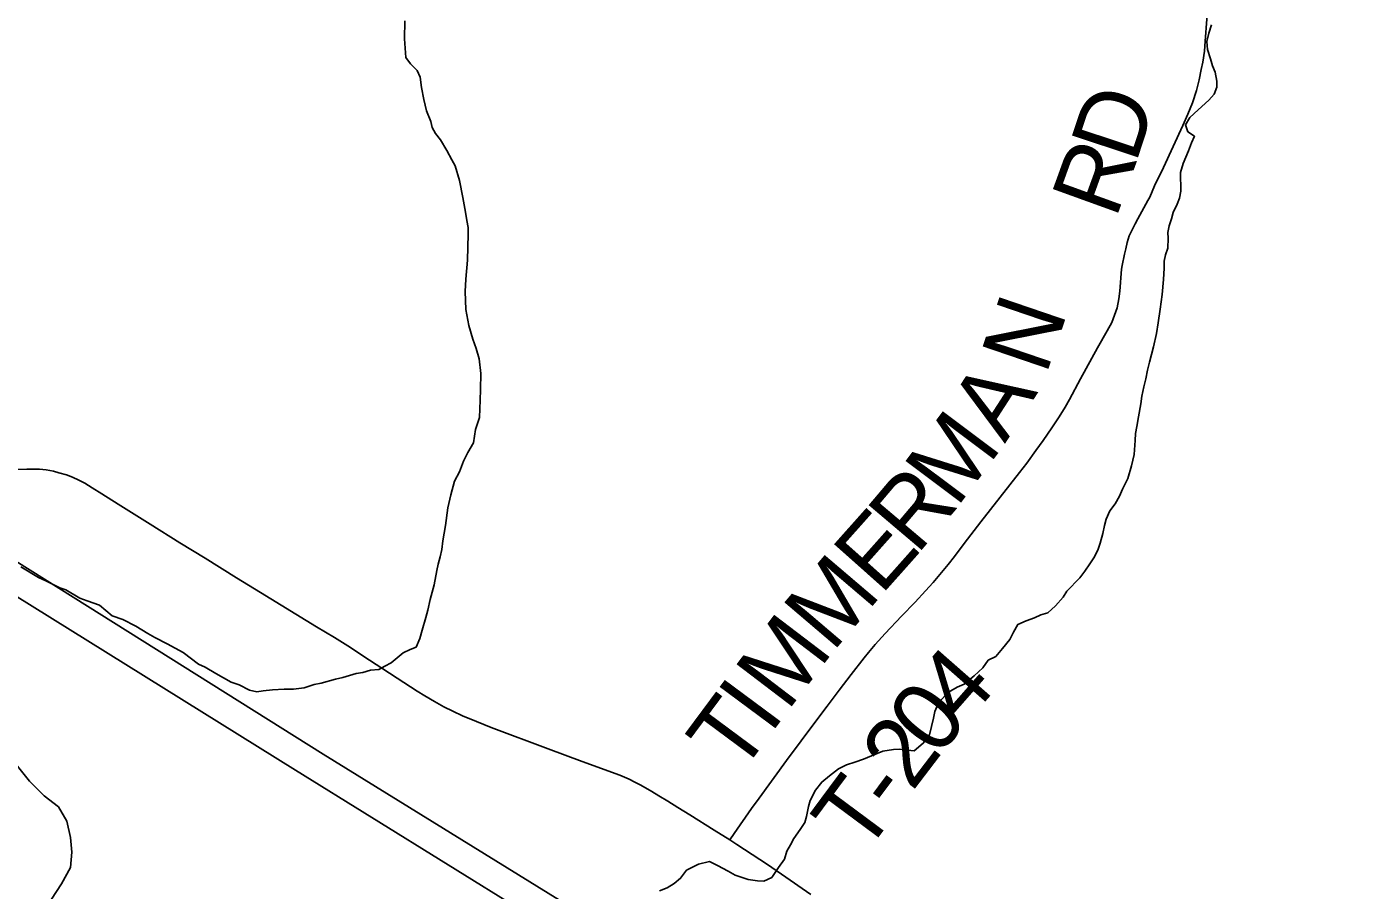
# Model space of a CAD drawing. Extents: x 0 to 34, y 0 to 22.
# Drawn here: x 6.594 to 7.678, y 17.126 to 17.833 of the extents above; entities that cross this region are included whole.
import ezdxf

# ---------------------------------------------------------------- set-up
doc = ezdxf.new("R2010")
doc.units = 0
for name, color, linetype in [('GM_X_County_Road', 7, 'Continuous'), ('GM_X_Interchange_Ramps', 7, 'Continuous'), ('GM_X_Interstate_Route', 7, 'Continuous'), ('GM_X_Section', 7, 'Continuous'), ('GM_X_Township_Road_Text', 7, 'Continuous'), ('GM_X_US_Location', 7, 'Continuous')]:
    doc.layers.add(name, color=color, linetype=linetype)

msp = doc.modelspace()

# ---------------------------------------------------------------- linework, layer by layer
at = {"layer": 'GM_X_County_Road'}
for points in [[(8.9, 16.3458), (8.8896, 16.3484), (8.8415, 16.3566), (8.7835, 16.3626), (8.6949, 16.3631), (8.0785, 16.3449), (8.0171, 16.3505), (7.9686, 16.3596), (7.9232, 16.3737), (7.8664, 16.3974), (7.8219, 16.4192), (7.7822, 16.4429), (7.7542, 16.4676), (7.7187, 16.4982), (7.6774, 16.5465), (7.4755, 16.7917), (7.4147, 16.863), (7.366, 16.9092), (7.315, 16.9447), (7.2325, 16.9942), (7.0394, 17.1127), (6.8369, 17.2379), (6.5407, 17.4237)], [(6.5677, 17.3781), (6.8144, 17.2247), (7.064, 17.07), (7.2695, 16.9425), (7.2777, 16.9375), (7.3019, 16.9255), (7.3143, 16.9173), (7.3316, 16.9061), (7.3452, 16.8969), (7.357, 16.888), (7.3696, 16.8779), (7.387, 16.8636), (7.4011, 16.8497), (7.4139, 16.8372), (7.4259, 16.8238), (7.4384, 16.8097), (7.5048, 16.7293), (7.5321, 16.6954), (7.592, 16.6219), (7.6516, 16.5487), (7.6743, 16.5214), (7.6872, 16.5062)]]:
    msp.add_lwpolyline(points, dxfattribs=at)
at = {"layer": 'GM_X_Interchange_Ramps'}
for points in [[(6.5874, 17.4706), (6.5946, 17.471)], [(6.5946, 17.471), (6.605, 17.4708), (6.6104, 17.4702), (6.6164, 17.4691), (6.6208, 17.468), (6.6271, 17.4661), (6.632, 17.4642), (6.6373, 17.4619), (6.642, 17.4594), (6.6481, 17.4557), (6.6559, 17.4508), (6.6693, 17.4422), (6.6955, 17.4258), (6.7197, 17.4107), (6.7405, 17.398), (6.7661, 17.3821), (6.7857, 17.3699), (6.8314, 17.3419), (6.8461, 17.3333), (6.8571, 17.3263), (6.8748, 17.3148), (6.9137, 17.2894), (6.9201, 17.2856), (6.928, 17.2808), (6.9355, 17.2765), (6.9428, 17.2729), (6.9509, 17.2692), (6.9622, 17.2645), (6.9743, 17.2597), (7.0207, 17.2423), (7.0486, 17.2319), (7.0793, 17.2207), (7.0869, 17.2174), (7.0917, 17.215), (7.0966, 17.2124), (7.1055, 17.2072), (7.1113, 17.2037), (7.1186, 17.1993), (7.1268, 17.1943), (7.1365, 17.1882), (7.1564, 17.1757), (7.1692, 17.1678), (7.1749, 17.1641), (7.2001, 17.1477), (7.2116, 17.1397), (7.2354, 17.1231)]]:
    msp.add_lwpolyline(points, dxfattribs=at)
at = {"layer": 'GM_X_Interstate_Route'}
msp.add_lwpolyline([(7.1692, 17.1678), (7.1729, 17.1729), (7.187, 17.1933), (7.1933, 17.2019), (7.2156, 17.2326), (7.2396, 17.2647), (7.2489, 17.2772), (7.2587, 17.2902), (7.2685, 17.3029), (7.279, 17.3166), (7.2826, 17.321), (7.2882, 17.3276), (7.2963, 17.3366), (7.3097, 17.3508), (7.3208, 17.3622), (7.3292, 17.3715), (7.3355, 17.3783), (7.3423, 17.3865), (7.3478, 17.393), (7.3529, 17.3996), (7.3609, 17.41), (7.3745, 17.4278), (7.4062, 17.4682), (7.412, 17.4758), (7.4195, 17.486), (7.4254, 17.4944), (7.4324, 17.5046), (7.4384, 17.5136), (7.4433, 17.5216), (7.4469, 17.5279), (7.4559, 17.5447), (7.4697, 17.57), (7.4777, 17.5839), (7.4816, 17.5909), (7.4838, 17.5967), (7.4859, 17.6028), (7.4873, 17.6102), (7.488, 17.6164), (7.4894, 17.6343), (7.49, 17.6375), (7.4919, 17.6467), (7.4929, 17.651), (7.4942, 17.6562), (7.4958, 17.6616), (7.4985, 17.6671), (7.5007, 17.6715), (7.5028, 17.6755), (7.5111, 17.6905), (7.5125, 17.6932), (7.5165, 17.7024), (7.5237, 17.7175), (7.5395, 17.7518), (7.5438, 17.761), (7.5476, 17.7705), (7.5508, 17.7806), (7.5528, 17.7891), (7.5547, 17.7977), (7.5559, 17.8035), (7.5573, 17.8125), (7.5579, 17.8208), (7.5606, 17.857)], dxfattribs=at)
at = {"layer": 'GM_X_Township_Road_Text'}
for points in [[(6.5897, 17.3909), (6.6042, 17.3824), (6.6103, 17.3795), (6.6217, 17.3739), (6.6267, 17.3721), (6.6381, 17.3654), (6.6439, 17.3632), (6.6541, 17.3596), (6.6645, 17.3509), (6.6732, 17.348), (6.6839, 17.3425), (6.6935, 17.3365), (6.6992, 17.3332), (6.7095, 17.328), (6.7224, 17.321), (6.7351, 17.3113), (6.7404, 17.3091), (6.7492, 17.3039), (6.7618, 17.2968), (6.7683, 17.2946), (6.7766, 17.2902), (6.7827, 17.2888), (6.788, 17.2896), (6.7956, 17.2905), (6.805, 17.291), (6.8126, 17.2911), (6.8213, 17.292), (6.8296, 17.2948), (6.8352, 17.296), (6.8469, 17.2992), (6.853, 17.3005), (6.8639, 17.3037), (6.8692, 17.3045), (6.8756, 17.3065), (6.8824, 17.307), (6.8873, 17.3098), (6.8926, 17.3125), (6.9023, 17.3207), (6.9079, 17.3234), (6.9128, 17.3254), (6.9158, 17.3323), (6.9179, 17.3392), (6.9208, 17.3495), (6.9226, 17.3556), (6.9244, 17.3644), (6.9276, 17.3763), (6.9297, 17.3881), (6.9308, 17.3931), (6.9326, 17.3992), (6.934, 17.4053), (6.9347, 17.4122), (6.9368, 17.4248), (6.9388, 17.4393), (6.9413, 17.45), (6.9442, 17.4611), (6.9483, 17.4687), (6.9515, 17.4775), (6.9552, 17.4845), (6.9597, 17.4925), (6.9614, 17.5032), (6.9647, 17.5132), (6.9652, 17.5273), (6.9655, 17.536), (6.9657, 17.549), (6.9644, 17.5611), (6.962, 17.5695), (6.9592, 17.5771), (6.956, 17.5884), (6.9536, 17.6014), (6.953, 17.6162), (6.9536, 17.6261), (6.9549, 17.6418), (6.9553, 17.6631), (6.9553, 17.6684), (6.9544, 17.6741), (6.9532, 17.681), (6.9511, 17.6931), (6.9483, 17.7068), (6.9447, 17.7189), (6.942, 17.7238), (6.9381, 17.7314), (6.9327, 17.7401), (6.9288, 17.7454), (6.9261, 17.7503), (6.9249, 17.7552), (6.9214, 17.7639), (6.9193, 17.773), (6.9173, 17.7829), (6.9161, 17.7913), (6.9137, 17.7969), (6.9083, 17.8022), (6.9045, 17.8075), (6.9035, 17.8227), (6.9037, 17.8375)], [(7.4976, 17.4736), (7.4997, 17.4828), (7.5007, 17.4943), (7.501, 17.5), (7.502, 17.5057), (7.5034, 17.5137), (7.5052, 17.5244), (7.5062, 17.5305), (7.5076, 17.5382), (7.5094, 17.5447), (7.5108, 17.5519), (7.5123, 17.5584), (7.5155, 17.571), (7.518, 17.5817), (7.5194, 17.5905), (7.5211, 17.6016), (7.5228, 17.6138), (7.5238, 17.626), (7.5244, 17.6352), (7.5243, 17.6409), (7.5254, 17.6462), (7.5272, 17.6516), (7.5275, 17.6596), (7.5274, 17.6645), (7.5285, 17.6699), (7.5303, 17.6756), (7.5317, 17.6806), (7.535, 17.6875), (7.5369, 17.6925), (7.5379, 17.6982), (7.5377, 17.7135), (7.5399, 17.7207), (7.5443, 17.7311), (7.5468, 17.7376), (7.549, 17.743), (7.5437, 17.7467), (7.5417, 17.7524), (7.5454, 17.7585), (7.5521, 17.7647), (7.5607, 17.7725), (7.5652, 17.7775), (7.5674, 17.7832), (7.5673, 17.7882), (7.5661, 17.7954), (7.5637, 17.8007), (7.5621, 17.8064), (7.5598, 17.814), (7.5593, 17.8204), (7.5607, 17.8273), (7.5629, 17.8342)], [(7.1118, 17.1262), (7.1182, 17.1286), (7.1238, 17.1321), (7.1291, 17.1364), (7.1339, 17.1429), (7.1437, 17.148), (7.1527, 17.15), (7.1592, 17.1467), (7.168, 17.1423), (7.1737, 17.1389), (7.1844, 17.1353), (7.1919, 17.1343), (7.1972, 17.134), (7.2036, 17.1371), (7.2092, 17.1452), (7.214, 17.1521), (7.2158, 17.1586), (7.2188, 17.1636), (7.2217, 17.169), (7.2269, 17.1763), (7.2306, 17.1821), (7.2321, 17.187), (7.2335, 17.1951), (7.2349, 17.2), (7.2393, 17.2085), (7.2445, 17.215), (7.2509, 17.2201), (7.258, 17.2259), (7.2648, 17.229), (7.2716, 17.2314), (7.2787, 17.2338), (7.2851, 17.2366), (7.2945, 17.2402), (7.3032, 17.2418), (7.3081, 17.2419), (7.3146, 17.2412), (7.3199, 17.2405), (7.3274, 17.2468), (7.3326, 17.2537), (7.3358, 17.2674), (7.3369, 17.2728), (7.3402, 17.2805), (7.348, 17.2886), (7.3551, 17.2925), (7.3608, 17.2952), (7.369, 17.3018), (7.3761, 17.3084), (7.3806, 17.3146), (7.3866, 17.3177), (7.3922, 17.3243), (7.3981, 17.3316), (7.4011, 17.3377), (7.4047, 17.3439), (7.4115, 17.347), (7.4183, 17.3494), (7.4236, 17.3518), (7.4292, 17.3534), (7.4356, 17.3592), (7.4419, 17.3662), (7.4449, 17.3712), (7.4553, 17.382), (7.4594, 17.3874), (7.4635, 17.3935), (7.4668, 17.3985), (7.4701, 17.4047), (7.472, 17.4104), (7.4741, 17.4184), (7.4755, 17.4249), (7.477, 17.4299), (7.4799, 17.4368), (7.4844, 17.4426), (7.4877, 17.4487), (7.4903, 17.4545), (7.4947, 17.4633), (7.4976, 17.4736)]]:
    msp.add_lwpolyline(points, dxfattribs=at)
at = {"layer": 'GM_X_US_Location'}
msp.add_lwpolyline([(6.5872, 17.2281), (6.5969, 17.2157), (6.6088, 17.2037), (6.6207, 17.1947), (6.6273, 17.1831), (6.6305, 17.1698), (6.6314, 17.1577), (6.6304, 17.1451), (6.623, 17.1318), (6.6148, 17.1192), (6.6069, 17.1069), (6.6029, 17.094)], dxfattribs=at)

# ---------------------------------------------------------------- texts
at = {"layer": 'GM_X_Section'}
for s, rotation, p in [('D', 71.7234, (7.501, 17.7199)), ('R', 70.1097, (7.4847, 17.6747)), ('N', 71.1616, (7.4277, 17.547)), ('A', 57.1902, (7.3941, 17.4914)), ('M', 53.1348, (7.3546, 17.4385)), ('R', 49.7413, (7.3221, 17.4)), ('E', 48.323, (7.2928, 17.3671)), ('M', 49.5663, (7.2531, 17.3204)), ('M', 52.7048, (7.2162, 17.272)), ('4', 48.7264, (7.3607, 17.261)), ('I', 53.4205, (7.2024, 17.2534)), ('T', 53.4215, (7.1771, 17.2193)), ('0', 51.3792, (7.3393, 17.2342)), ('2', 52.6545, (7.3183, 17.2066)), ('T', 53.4215, (7.2791, 17.154)), ('-', 53.2409, (7.3044, 17.1881))]:
    msp.add_text(s, height=0.0568, rotation=rotation, dxfattribs=at).set_placement(p)

doc.saveas('drawing.dxf')
